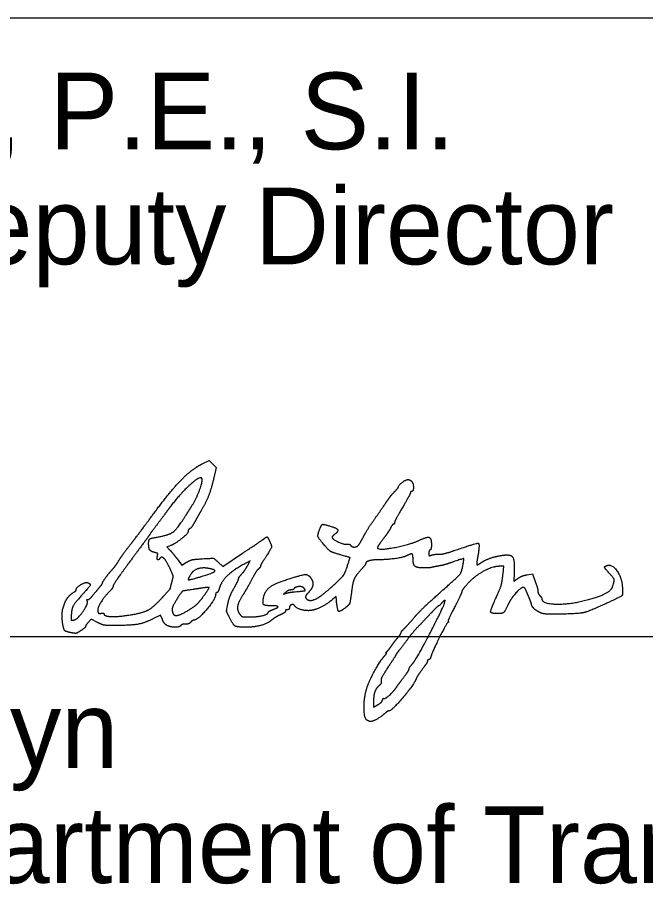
# Model space of a CAD drawing. Extents: x -8.3 to 42.1, y 0 to 22.
# Drawn here: x 25.676 to 26.821, y 7.305 to 8.926 of the extents above; entities that cross this region are included whole.
import ezdxf

# ---------------------------------------------------------------- set-up
doc = ezdxf.new("R2010")
doc.units = 0
doc.layers.add('SH_Data', color=7, linetype='Continuous')
doc.layers.add('SH_Text', color=7, linetype='Continuous')

msp = doc.modelspace()

# ---------------------------------------------------------------- linework, layer by layer
at = {"layer": 'SH_Data'}
for p, q in [((24.5279, 8.9262), (28.0279, 8.9262)), ((24.5279, 7.7968), (28.0279, 7.7968))]:
    msp.add_line(p, q, dxfattribs=at)
at = {"layer": 'SH_Text'}
for points in [[(26.0131, 8.112), (26.0258, 8.1179), (26.0321, 8.1115), (26.0385, 8.1051), (26.0341, 8.0864)], [(25.9532, 7.962), (25.9482, 7.9605), (25.9534, 7.9553)], [(26.0422, 7.9323), (26.0503, 7.9247), (26.0866, 7.9488)], [(25.967, 7.9386), (25.9756, 7.9271), (25.9844, 7.9323)], [(26.0961, 7.9271), (26.1005, 7.935), (26.095, 7.9321)], [(26.5619, 7.9112), (26.5634, 7.925), (26.5556, 7.925)], [(26.6058, 7.9095), (26.6154, 7.9111), (26.6205, 7.8975)], [(26.2578, 7.8634), (26.2572, 7.8702), (26.2513, 7.8651)], [(25.9402, 7.8278), (25.9369, 7.8358), (25.923, 7.829)], [(25.8216, 7.8227), (25.8101, 7.8285), (25.805, 7.8227)], [(26.3256, 7.6773), (26.3256, 7.6679), (26.3331, 7.6722)]]:
    msp.add_lwpolyline(points, dxfattribs=at)
for points in [[(25.9236, 8.0201), (25.9533, 8.0607), (25.9951, 8.1036), (26.0131, 8.112)], [(26.0117, 8.0862), (26.008, 8.0899), (25.9695, 8.0541), (25.9541, 8.0328)], [(25.9934, 8.0342), (26.0028, 8.049), (26.0148, 8.0831), (26.0117, 8.0862)], [(26.0341, 8.0864), (26.0291, 8.0653), (26.0199, 8.0417), (26.0105, 8.0258)], [(26.3712, 8.0701), (26.3712, 8.0729), (26.3844, 8.0832), (26.3881, 8.0833)], [(26.3881, 8.0833), (26.3901, 8.0833), (26.3931, 8.0821), (26.3947, 8.0805)], [(26.3947, 8.0805), (26.3982, 8.077), (26.3986, 8.0618), (26.3952, 8.0618)], [(26.3508, 8.0448), (26.3547, 8.0506), (26.361, 8.0583), (26.3646, 8.062)], [(26.3646, 8.062), (26.3682, 8.0656), (26.3712, 8.0693), (26.3712, 8.0701)], [(26.3952, 8.0618), (26.3939, 8.0618), (26.3928, 8.0606), (26.3928, 8.0592)], [(26.3292, 8.0138), (26.3371, 8.025), (26.3468, 8.0389), (26.3508, 8.0448)], [(26.3928, 8.0592), (26.3928, 8.0579), (26.3863, 8.0458), (26.3784, 8.0324)], [(25.9541, 8.0328), (25.9505, 8.0279), (25.9411, 8.0152), (25.9332, 8.0047)], [(25.9829, 8.0175), (25.9861, 8.0227), (25.9909, 8.0302), (25.9934, 8.0342)], [(26.3784, 8.0324), (26.3705, 8.019), (26.364, 8.0066), (26.364, 8.0049)], [(25.8834, 7.9667), (25.8923, 7.978), (25.9104, 8.0021), (25.9236, 8.0201)], [(25.9331, 7.9788), (25.9537, 7.9826), (25.9677, 7.9935), (25.9829, 8.0175)], [(26.0105, 8.0258), (26.007, 8.0198), (26.0018, 8.0106), (25.9989, 8.0054)], [(26.3078, 7.9802), (26.3116, 7.9874), (26.3212, 8.0025), (26.3292, 8.0138)], [(25.9332, 8.0047), (25.9253, 7.9942), (25.9172, 7.9832), (25.9152, 7.9803)], [(25.9989, 8.0054), (25.9961, 8.0001), (25.9923, 7.9949), (25.9905, 7.9938)], [(26.2271, 7.992), (26.2309, 8.0011), (26.234, 8.0021), (26.2467, 7.9983)], [(26.2467, 7.9983), (26.2587, 7.9948), (26.2616, 7.9886), (26.2539, 7.9828)], [(26.3567, 7.9952), (26.3549, 7.9915), (26.3488, 7.9824), (26.3431, 7.975)], [(26.362, 8.0018), (26.3609, 8.0018), (26.3585, 7.9988), (26.3567, 7.9952)], [(26.364, 8.0049), (26.364, 8.0032), (26.3631, 8.0018), (26.362, 8.0018)], [(25.9152, 7.9803), (25.9132, 7.9773), (25.8978, 7.9564), (25.881, 7.9337)], [(25.9152, 7.9667), (25.9152, 7.9736), (25.9193, 7.9764), (25.9331, 7.9788)], [(25.9872, 7.9884), (25.9872, 7.9847), (25.9614, 7.9646), (25.9532, 7.962)], [(25.9905, 7.9938), (25.9887, 7.9928), (25.9872, 7.9904), (25.9872, 7.9884)], [(26.1257, 7.9753), (26.1302, 7.9791), (26.1326, 7.9782), (26.1356, 7.9716)], [(26.2369, 7.9626), (26.2254, 7.9757), (26.2232, 7.9824), (26.2271, 7.992)], [(26.2539, 7.9828), (26.2512, 7.9807), (26.2497, 7.9778), (26.2506, 7.9765)], [(26.2985, 7.964), (26.2998, 7.9656), (26.304, 7.9729), (26.3078, 7.9802)], [(25.8619, 7.9373), (25.8648, 7.9421), (25.8745, 7.9553), (25.8834, 7.9667)], [(25.9262, 7.9503), (25.919, 7.9521), (25.9152, 7.9578), (25.9152, 7.9667)], [(26.0866, 7.9488), (26.1065, 7.9621), (26.1241, 7.974), (26.1257, 7.9753)], [(26.1356, 7.9716), (26.14, 7.962), (26.139, 7.9579), (26.1288, 7.942)], [(26.2604, 7.9474), (26.2496, 7.9506), (26.2447, 7.9537), (26.2369, 7.9626)], [(26.2506, 7.9765), (26.2533, 7.9727), (26.2732, 7.9645), (26.2778, 7.9653)], [(26.2778, 7.9653), (26.2801, 7.9657), (26.2827, 7.9649), (26.2835, 7.9635)], [(26.2835, 7.9635), (26.2857, 7.96), (26.2957, 7.9603), (26.2985, 7.964)], [(26.3431, 7.975), (26.3374, 7.9675), (26.3328, 7.9602), (26.3328, 7.9589)], [(26.3328, 7.9589), (26.3328, 7.9536), (26.3924, 7.9646), (26.4104, 7.9731)], [(26.4104, 7.9731), (26.4233, 7.9793), (26.4312, 7.9762), (26.4312, 7.9648)], [(26.4312, 7.9648), (26.4312, 7.9602), (26.4301, 7.9558), (26.4288, 7.955)], [(26.4735, 7.954), (26.5139, 7.9679), (26.5198, 7.9663), (26.5157, 7.9424)], [(25.9313, 7.9441), (25.9322, 7.9476), (25.9309, 7.9491), (25.9262, 7.9503)], [(25.9534, 7.9553), (25.9562, 7.9525), (25.9623, 7.945), (25.967, 7.9386)], [(26.2772, 7.9237), (26.2828, 7.9405), (26.2825, 7.9411), (26.2604, 7.9474)], [(26.3976, 7.9396), (26.3976, 7.9469), (26.3939, 7.9485), (26.3861, 7.9443)], [(26.4288, 7.955), (26.4275, 7.9541), (26.4264, 7.9513), (26.4264, 7.9487)], [(26.4264, 7.9487), (26.4264, 7.9447), (26.4274, 7.9442), (26.4318, 7.9456)], [(26.4318, 7.9456), (26.4348, 7.9465), (26.4406, 7.9472), (26.4447, 7.947)], [(26.4447, 7.947), (26.4489, 7.9468), (26.4618, 7.95), (26.4735, 7.954)], [(25.8456, 7.9154), (25.8522, 7.9228), (25.8564, 7.9285), (25.8619, 7.9373)], [(25.881, 7.9337), (25.8643, 7.9111), (25.8505, 7.8909), (25.8504, 7.889)], [(25.9355, 7.9393), (25.9331, 7.9354), (25.9299, 7.9389), (25.9313, 7.9441)], [(25.9543, 7.9207), (25.9482, 7.9344), (25.9385, 7.944), (25.9355, 7.9393)], [(25.9844, 7.9323), (25.9909, 7.9362), (25.9985, 7.9379), (26.0136, 7.9388)], [(26.0136, 7.9388), (26.0339, 7.94), (26.0341, 7.9399), (26.0422, 7.9323)], [(26.095, 7.9321), (26.0716, 7.9195), (26.0488, 7.8989), (26.0447, 7.8864)], [(26.1288, 7.942), (26.1235, 7.9339), (26.1192, 7.9263), (26.1192, 7.9252)], [(26.3354, 7.937), (26.3239, 7.937), (26.3112, 7.9332), (26.3112, 7.9298)], [(26.3861, 7.9443), (26.3806, 7.9413), (26.3504, 7.937), (26.3354, 7.937)], [(26.4169, 7.922), (26.4045, 7.922), (26.3976, 7.9283), (26.3976, 7.9396)], [(26.4682, 7.9321), (26.4604, 7.9294), (26.4507, 7.9266), (26.4468, 7.926)], [(26.4888, 7.9274), (26.4909, 7.9389), (26.4891, 7.9393), (26.4682, 7.9321)], [(26.5157, 7.9424), (26.5143, 7.9348), (26.5136, 7.9282), (26.5141, 7.9277)], [(26.5141, 7.9277), (26.5145, 7.9272), (26.5179, 7.929), (26.5216, 7.9316)], [(26.5216, 7.9316), (26.5289, 7.9366), (26.5471, 7.9429), (26.5608, 7.9451)], [(26.5608, 7.9451), (26.5754, 7.9474), (26.5831, 7.937), (26.5823, 7.9157)], [(25.8312, 7.895), (25.8312, 7.8966), (25.8403, 7.9096), (25.8456, 7.9154)], [(25.9576, 7.8962), (25.9602, 7.906), (25.9599, 7.9082), (25.9543, 7.9207)], [(26.0254, 7.921), (26.0145, 7.9232), (25.9971, 7.9181), (25.9928, 7.9115)], [(26.0148, 7.9075), (26.034, 7.9134), (26.038, 7.9185), (26.0254, 7.921)], [(26.0833, 7.9089), (26.0887, 7.9149), (26.0912, 7.9185), (26.0961, 7.9271)], [(26.1156, 7.9202), (26.1137, 7.9186), (26.1106, 7.9144), (26.1087, 7.9109)], [(26.1192, 7.9252), (26.1192, 7.9241), (26.1176, 7.9218), (26.1156, 7.9202)], [(26.2589, 7.8964), (26.2693, 7.9064), (26.2734, 7.9126), (26.2772, 7.9237)], [(26.3018, 7.9177), (26.2933, 7.9083), (26.2876, 7.8957), (26.286, 7.883)], [(26.3112, 7.9298), (26.3112, 7.9289), (26.307, 7.9235), (26.3018, 7.9177)], [(26.4336, 7.9234), (26.4303, 7.9226), (26.4228, 7.922), (26.4169, 7.922)], [(26.4468, 7.926), (26.4428, 7.9253), (26.4369, 7.9242), (26.4336, 7.9234)], [(26.4439, 7.8744), (26.4795, 7.906), (26.4864, 7.9142), (26.4888, 7.9274)], [(26.5556, 7.925), (26.5429, 7.925), (26.5091, 7.9065), (26.4969, 7.893)], [(26.5823, 7.9157), (26.5816, 7.8973), (26.5815, 7.8976), (26.5892, 7.9031)], [(26.7524, 7.9163), (26.7471, 7.922), (26.7468, 7.9247), (26.7515, 7.9264)], [(26.7515, 7.9264), (26.76, 7.9297), (26.7785, 7.9048), (26.7795, 7.8885)], [(26.7615, 7.8872), (26.7655, 7.899), (26.7639, 7.9039), (26.7524, 7.9163)], [(25.9928, 7.9115), (25.9858, 7.9008), (25.9903, 7.9), (26.0148, 7.9075)], [(26.0708, 7.8848), (26.0752, 7.8925), (26.079, 7.9002), (26.0793, 7.9019)], [(26.0793, 7.9019), (26.0796, 7.9037), (26.0813, 7.9068), (26.0833, 7.9089)], [(26.1087, 7.9109), (26.1006, 7.8955), (26.0928, 7.8817), (26.0867, 7.872)], [(26.1249, 7.8681), (26.1271, 7.8794), (26.1433, 7.8928), (26.1626, 7.8992)], [(26.1626, 7.8992), (26.1944, 7.9098), (26.2078, 7.9102), (26.2129, 7.9008)], [(26.2129, 7.9008), (26.2161, 7.8947), (26.2127, 7.8833), (26.2053, 7.8754)], [(26.5472, 7.8633), (26.5563, 7.8832), (26.5603, 7.8964), (26.5619, 7.9112)], [(26.5892, 7.9031), (26.593, 7.9058), (26.6004, 7.9087), (26.6058, 7.9095)], [(26.6205, 7.8975), (26.6233, 7.8901), (26.6256, 7.8819), (26.6256, 7.8794)], [(25.7785, 7.8776), (25.7811, 7.8792), (25.7832, 7.8816), (25.7832, 7.8829)], [(25.7832, 7.8829), (25.7833, 7.8867), (25.8, 7.8967), (25.8038, 7.8952)], [(25.8038, 7.8952), (25.8098, 7.8929), (25.8075, 7.888), (25.7932, 7.8721)], [(25.8167, 7.8758), (25.822, 7.8824), (25.8275, 7.8891), (25.8288, 7.8907)], [(25.8288, 7.8907), (25.8301, 7.8923), (25.8312, 7.8942), (25.8312, 7.895)], [(25.8504, 7.889), (25.8503, 7.887), (25.847, 7.8822), (25.843, 7.8782)], [(25.938, 7.8657), (25.9541, 7.8832), (25.9544, 7.8838), (25.9576, 7.8962)], [(25.9956, 7.8827), (25.9778, 7.8801), (25.9758, 7.879), (25.9685, 7.8678)], [(26.013, 7.8854), (26.0074, 7.8845), (25.9995, 7.8833), (25.9956, 7.8827)], [(26.018, 7.8737), (26.0258, 7.8851), (26.0249, 7.8872), (26.013, 7.8854)], [(26.0447, 7.8864), (26.043, 7.8812), (26.0407, 7.877), (26.0396, 7.877)], [(26.0599, 7.857), (26.0615, 7.8647), (26.0664, 7.8772), (26.0708, 7.8848)], [(26.1747, 7.8818), (26.1724, 7.8818), (26.1684, 7.88), (26.1658, 7.878)], [(26.1802, 7.8839), (26.1795, 7.8827), (26.177, 7.8818), (26.1747, 7.8818)], [(26.1987, 7.885), (26.1959, 7.8884), (26.1825, 7.8876), (26.1802, 7.8839)], [(26.1828, 7.8786), (26.1995, 7.8801), (26.2019, 7.8811), (26.1987, 7.885)], [(26.2019, 7.8675), (26.2072, 7.8589), (26.2339, 7.8724), (26.2589, 7.8964)], [(26.286, 7.883), (26.2832, 7.8605), (26.2814, 7.855), (26.2758, 7.8505)], [(26.4969, 7.893), (26.4911, 7.8865), (26.4864, 7.88), (26.4864, 7.8784)], [(26.5988, 7.8866), (26.5945, 7.8866), (26.5762, 7.8661), (26.5715, 7.8559)], [(26.6044, 7.88), (26.6029, 7.8836), (26.6004, 7.8866), (26.5988, 7.8866)], [(26.7126, 7.863), (26.7363, 7.8692), (26.7593, 7.8806), (26.7615, 7.8872)], [(26.7795, 7.8885), (26.7804, 7.8732), (26.7778, 7.8701), (26.7544, 7.8591)], [(25.7583, 7.8213), (25.7554, 7.8398), (25.7661, 7.8699), (25.7785, 7.8776)], [(25.7932, 7.8721), (25.7795, 7.857), (25.7745, 7.8468), (25.7739, 7.833)], [(25.8044, 7.8645), (25.8058, 7.8641), (25.8113, 7.8692), (25.8167, 7.8758)], [(25.843, 7.8782), (25.8332, 7.8686), (25.8208, 7.8465), (25.8226, 7.8418)], [(25.8815, 7.8363), (25.9042, 7.84), (25.9238, 7.8502), (25.938, 7.8657)], [(25.9685, 7.8678), (25.9603, 7.8551), (25.9571, 7.8453), (25.9593, 7.8395)], [(25.9881, 7.845), (25.9993, 7.852), (26.0102, 7.8626), (26.018, 7.8737)], [(26.0375, 7.874), (26.0374, 7.8654), (26.0043, 7.8266), (25.9972, 7.8266)], [(26.0396, 7.877), (26.0385, 7.877), (26.0376, 7.8756), (26.0375, 7.874)], [(26.0867, 7.872), (26.0787, 7.8594), (26.0765, 7.8442), (26.0816, 7.8374)], [(26.1385, 7.853), (26.127, 7.853), (26.1229, 7.8575), (26.1249, 7.8681)], [(26.1658, 7.878), (26.1612, 7.8742), (26.1612, 7.8742), (26.166, 7.8759)], [(26.166, 7.8759), (26.1686, 7.8768), (26.1762, 7.878), (26.1828, 7.8786)], [(26.2053, 7.8754), (26.2025, 7.8725), (26.201, 7.869), (26.2019, 7.8675)], [(26.2513, 7.8651), (26.2419, 7.8569), (26.2219, 7.8463), (26.2128, 7.8446)], [(26.3999, 7.8317), (26.4071, 7.8401), (26.4269, 7.8593), (26.4439, 7.8744)], [(26.4864, 7.8784), (26.4864, 7.8768), (26.4804, 7.864), (26.4732, 7.8498)], [(26.6103, 7.8658), (26.6085, 7.87), (26.6058, 7.8763), (26.6044, 7.88)], [(26.6137, 7.8562), (26.6136, 7.8573), (26.6121, 7.8616), (26.6103, 7.8658)], [(26.6256, 7.8794), (26.6256, 7.8769), (26.6272, 7.8733), (26.6292, 7.8713)], [(26.6292, 7.8713), (26.6312, 7.8693), (26.6328, 7.8666), (26.6328, 7.8653)], [(26.6328, 7.8653), (26.6328, 7.8568), (26.6834, 7.8553), (26.7126, 7.863)], [(25.7787, 7.827), (25.7851, 7.8279), (25.8052, 7.8564), (25.8032, 7.8616)], [(25.8032, 7.8616), (25.8024, 7.8635), (25.803, 7.8648), (25.8044, 7.8645)], [(26.0619, 7.833), (26.0575, 7.8421), (26.0573, 7.8443), (26.0599, 7.857)], [(26.1419, 7.846), (26.1522, 7.8498), (26.1506, 7.853), (26.1385, 7.853)], [(26.172, 7.8491), (26.172, 7.8473), (26.1704, 7.8458), (26.1684, 7.8458)], [(26.1815, 7.8531), (26.1795, 7.8564), (26.172, 7.8532), (26.172, 7.8491)], [(26.2128, 7.8446), (26.2042, 7.8431), (26.1844, 7.8484), (26.1815, 7.8531)], [(26.2758, 7.8505), (26.264, 7.8413), (26.2597, 7.8444), (26.2578, 7.8634)], [(26.3973, 7.7479), (26.4049, 7.7566), (26.4582, 7.8604), (26.4561, 7.8624)], [(26.4446, 7.853), (26.4438, 7.853), (26.4399, 7.8494), (26.4358, 7.8452)], [(26.4504, 7.8584), (26.448, 7.8554), (26.4454, 7.853), (26.4446, 7.853)], [(26.4561, 7.8624), (26.4554, 7.8632), (26.4528, 7.8613), (26.4504, 7.8584)], [(26.4732, 7.8498), (26.4659, 7.8357), (26.4607, 7.8241), (26.4618, 7.8241)], [(26.5546, 7.8386), (26.5401, 7.8386), (26.5385, 7.844), (26.5472, 7.8633)], [(26.5715, 7.8559), (26.5658, 7.8435), (26.5609, 7.8386), (26.5546, 7.8386)], [(26.6293, 7.8406), (26.6223, 7.844), (26.6138, 7.8524), (26.6137, 7.8562)], [(26.7544, 7.8591), (26.7196, 7.8428), (26.6985, 7.838), (26.6592, 7.8376)], [(25.7739, 7.833), (25.7737, 7.8274), (25.7745, 7.8264), (25.7787, 7.827)], [(25.8226, 7.8418), (25.8235, 7.8394), (25.8258, 7.8385), (25.8288, 7.8393)], [(25.8288, 7.8393), (25.8314, 7.8399), (25.8336, 7.8396), (25.8336, 7.8385)], [(25.8336, 7.8385), (25.8336, 7.8339), (25.8592, 7.8327), (25.8815, 7.8363)], [(25.9593, 7.8395), (25.9614, 7.8342), (25.9749, 7.8369), (25.9881, 7.845)], [(26.0937, 7.8138), (26.0762, 7.8139), (26.0692, 7.8182), (26.0619, 7.833)], [(26.0816, 7.8374), (26.0844, 7.8336), (26.088, 7.8326), (26.0992, 7.8326)], [(26.0992, 7.8326), (26.1132, 7.8326), (26.1336, 7.8377), (26.1336, 7.8412)], [(26.1336, 7.8412), (26.1336, 7.8422), (26.1373, 7.8444), (26.1419, 7.846)], [(26.1594, 7.8384), (26.152, 7.8351), (26.1444, 7.8306), (26.1402, 7.8271)], [(26.1648, 7.8433), (26.1648, 7.8419), (26.1624, 7.8397), (26.1594, 7.8384)], [(26.1684, 7.8458), (26.1664, 7.8458), (26.1648, 7.8447), (26.1648, 7.8433)], [(26.4358, 7.8452), (26.4317, 7.8409), (26.4212, 7.8298), (26.4124, 7.8205)], [(26.6592, 7.8376), (26.6442, 7.8374), (26.6339, 7.8385), (26.6293, 7.8406)], [(25.7749, 7.8036), (25.764, 7.8056), (25.7602, 7.8097), (25.7583, 7.8213)], [(25.805, 7.8227), (25.8022, 7.8195), (25.8, 7.8161), (25.8, 7.8151)], [(25.8524, 7.817), (25.8368, 7.817), (25.8309, 7.8181), (25.8216, 7.8227)], [(25.923, 7.829), (25.9074, 7.8212), (25.8823, 7.817), (25.8524, 7.817)], [(25.9484, 7.8172), (25.9458, 7.8186), (25.9421, 7.8234), (25.9402, 7.8278)], [(25.974, 7.817), (25.972, 7.8138), (25.9545, 7.8139), (25.9484, 7.8172)], [(25.9822, 7.8194), (25.9785, 7.8194), (25.9748, 7.8183), (25.974, 7.817)], [(25.992, 7.823), (25.9903, 7.821), (25.9859, 7.8194), (25.9822, 7.8194)], [(25.9972, 7.8266), (25.996, 7.8266), (25.9936, 7.8249), (25.992, 7.823)], [(26.1402, 7.8271), (26.1325, 7.8207), (26.1082, 7.8138), (26.0937, 7.8138)], [(26.3814, 7.8113), (26.3844, 7.8141), (26.3927, 7.8233), (26.3999, 7.8317)], [(26.4124, 7.8205), (26.4036, 7.8113), (26.3937, 7.8), (26.3904, 7.7955)], [(26.461, 7.8223), (26.4583, 7.8205), (26.4331, 7.7695), (26.4301, 7.76)], [(26.4618, 7.8241), (26.4628, 7.8241), (26.4624, 7.8233), (26.461, 7.8223)], [(25.7916, 7.8077), (25.7851, 7.8032), (25.7815, 7.8023), (25.7749, 7.8036)], [(25.8, 7.8151), (25.8, 7.8142), (25.7962, 7.8108), (25.7916, 7.8077)], [(26.3694, 7.7943), (26.373, 7.7985), (26.376, 7.8029), (26.376, 7.8041)], [(26.376, 7.8041), (26.376, 7.8052), (26.3785, 7.8085), (26.3814, 7.8113)], [(26.3592, 7.7809), (26.3612, 7.784), (26.3658, 7.79), (26.3694, 7.7943)], [(26.3904, 7.7955), (26.3823, 7.7846), (26.3718, 7.7708), (26.3688, 7.7673)], [(26.3488, 7.7666), (26.3479, 7.7666), (26.3491, 7.7685), (26.3514, 7.771)], [(26.3514, 7.771), (26.3537, 7.7734), (26.3572, 7.7779), (26.3592, 7.7809)], [(26.3154, 7.7086), (26.3213, 7.7234), (26.3384, 7.7533), (26.3455, 7.7612)], [(26.3455, 7.7612), (26.3482, 7.7641), (26.3497, 7.7666), (26.3488, 7.7666)], [(26.3664, 7.7634), (26.3664, 7.7628), (26.36, 7.7529), (26.3523, 7.7413)], [(26.3688, 7.7673), (26.3675, 7.7657), (26.3664, 7.7639), (26.3664, 7.7634)], [(26.424, 7.7521), (26.424, 7.7507), (26.4197, 7.7439), (26.4145, 7.737)], [(26.4262, 7.7546), (26.425, 7.7546), (26.424, 7.7534), (26.424, 7.7521)], [(26.4301, 7.76), (26.4292, 7.757), (26.4274, 7.7546), (26.4262, 7.7546)], [(26.3523, 7.7413), (26.3436, 7.7282), (26.3387, 7.7185), (26.3394, 7.7158)], [(26.3802, 7.7217), (26.3858, 7.7291), (26.3904, 7.7362), (26.3904, 7.7376)], [(26.3904, 7.7376), (26.3904, 7.7389), (26.3935, 7.7435), (26.3973, 7.7479)], [(26.4145, 7.737), (26.4093, 7.7301), (26.4042, 7.7221), (26.4031, 7.7193)], [(26.4031, 7.7193), (26.3994, 7.7094), (26.3583, 7.661), (26.3536, 7.661)], [(26.3676, 7.7045), (26.3689, 7.7066), (26.3746, 7.7144), (26.3802, 7.7217)], [(26.3136, 7.6441), (26.3076, 7.6479), (26.3089, 7.6922), (26.3154, 7.7086)], [(26.3357, 7.7072), (26.3298, 7.7019), (26.3256, 7.6896), (26.3256, 7.6773)], [(26.3394, 7.7158), (26.34, 7.7132), (26.3385, 7.7096), (26.3357, 7.7072)], [(26.3448, 7.6838), (26.3467, 7.6826), (26.3633, 7.6977), (26.3676, 7.7045)], [(26.3331, 7.6722), (26.3373, 7.6746), (26.3412, 7.6784), (26.3418, 7.6807)], [(26.3418, 7.6807), (26.3424, 7.683), (26.3438, 7.6844), (26.3448, 7.6838)], [(26.3461, 7.6564), (26.3399, 7.6507), (26.324, 7.6417), (26.3201, 7.6418)], [(26.3536, 7.661), (26.3522, 7.661), (26.3489, 7.6589), (26.3461, 7.6564)], [(26.3201, 7.6418), (26.3185, 7.6418), (26.3156, 7.6429), (26.3136, 7.6441)]]:
    msp.add_open_spline(points, degree=2, dxfattribs=at)

# ---------------------------------------------------------------- texts
for s, p in [('Pat McColley, P.E., S.I.', (24.5279, 8.6862)), ('District       Deputy Director', (24.5279, 8.4762)), ('Pamela Boratyn', (24.5279, 7.5568)), ('Director, Department of Transportation', (24.5279, 7.3468))]:
    msp.add_text(s, height=0.14, dxfattribs=at).set_placement(p)

doc.saveas('drawing.dxf')
